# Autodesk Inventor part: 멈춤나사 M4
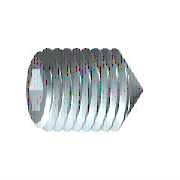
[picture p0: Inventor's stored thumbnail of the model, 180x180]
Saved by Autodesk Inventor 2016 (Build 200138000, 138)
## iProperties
Created: 2012-02
Part Number: 멈춤나사 M4
Material: 강철, 연강
Description: 6각 소켓 머리 없는 멈춤 나사
Document SubType Name: Modeling
Standard: KS B 1028
Designer: mduedu
Standards Organization: KS
Language: ko-KR
Size Designation: 원추점 M4x10
Categories: <MemberInstance><Categories><Category DisplayName="조임쇠" InternalName="e4da775c-781d-43d5-af7c-5136215cf5a6" Mnemonic="FSTN"><Category DisplayName="볼트" InternalN
Density: 7.86 g/cm^3
Mass: 0.792069 g
Surface Area: 1.48192 cm^2
Volume: 0.100772 cm^3
Appearance: 강철
Author: mduedu
IsCustomPart: 1
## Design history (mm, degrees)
sketch "스케치1"
  geometry: L1 (0, 0)-(6.833, 0); L2 (10, 1.155)-(10, 2); L3 (10, 2)-(0, 2); L4 (10, 1.155)-(7.5, 1.155); L5 (7.5, 1.155)-(6.833, 0); L6 (0, -0.4)-(0, 2.4) reference; L7 (0, 2)-(0, 0)
  constraints: 13 end point, 3 parallel, 1 collinear, 1 perpendicular, 1 point on line
  dimensions: "d0" = 2.5 distance of L2.start L4.end (= INTI); "d1" = 60 deg angle of L5 L1; "d2" = 4 diameter of L3 L1 (= NND); "d3" = 2.3094 diameter of L4 L1 (= 1.1547 x SW); "d5" = 10 distance from line of L2 L3.end (= NLG)
revolve "본체" sketch "스케치1" stored, may be unused: angle "d6" = 90 deg
sketch "스케치2"
  geometry: L1 (-0.577, 1)-(0.577, 1); L2 (0.577, 1)-(1.155, 0); L3 (1.155, 0)-(0.577, -1); L4 (0.577, -1)-(-0.577, -1); L5 (-0.577, -1)-(-1.155, 0); L6 (-1.155, 0)-(-0.577, 1); 3 further points
  constraints: 12 end point, 1 coincident, 1 horizontal, 13 other
extrude "슬롯" join sketch "스케치2" taper "d7" = 0 deg; stored distance "d21" = 10
workaxis "Work Axis1"
workplane "Work Plane1"
sketch "스케치4"
  geometry: L1 (-5, 0.2)-(-3.2, 2) reference; L2 (-5, -0.2)-(-3.2, -2) reference; L3 (-3.2, 2)-(-5.2, 0); L4 (-3.2, -2)-(-5.2, 0); 2 further points
  constraints: 4 end point, 2 collinear, 1 coincident
body "Solid1"
feature "스레드" dims "d12" = 10 (= NLG), "d13" = 0
chamfer "모따기1" distance "d8" = 1.8 (computed from NND, SPD, FAWI); stored, may be unused: angle "d9" = 45 deg (= FAWI), second distance "d34" = 1.8 (computed from NND, SPD, FAWI)
chamfer "모따기2" distance "d10" = 0.42941 (= -0.5 x GD1 + 0.5 x NND); stored, may be unused: angle "d11" = 45 deg (= FAWI), second distance "d35" = 0.42941 (= -0.5 x GD1 + 0.5 x NND)
other parameters: "NND" = 4 [user parameter; used in 5 equation terms], "NLG" = 10 [user parameter; used in 2 equation terms], "INTI" = 2.5 [user parameter; used in 1 equation term], "FAWI" = 45 deg [user parameter; used in 4 equation terms], "SW" = 2 [user parameter; used in 2 equation terms], "GD1" = 3.14117 (= THREADDIA - 1.2269 x PTC) [user parameter; used in 2 equation terms], "d4" = 0, "FAWI1" = 45 deg [user parameter], "SPD" = 0.4 [user parameter; used in 2 equation terms], "d36" = 0, "d37" = 0, "GUL" = 0.42941 (= 0.61345 x PTC) [user parameter], "TPU" = 14.28571 (computed from PTC) [user parameter], "TOA" = 30 deg [user parameter], "THREADDIA" = 4 [user parameter; used in 1 equation term], "PTC" = 0.7 [user parameter; used in 4 equation terms], "GAL" = 0.42941 (= 0.61345 x PTC) [user parameter], "E0" = 2.31 (= 1.155 x SW) [user parameter]
